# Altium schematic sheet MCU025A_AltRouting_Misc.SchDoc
size 431 x 279 mm; Date: Not shown in title block; ApprovedBy: Not shown in title block; CheckedBy: Not shown in title block; Author: Not shown in title block; CompanyName: Not shown in title block; Engineer: Not shown in title block; Organization: Not shown in title block; Address1: Not shown in title block; Address2: Not shown in title block; Address3: Not shown in title block; Address4: Not shown in title block; DocumentNumber: 3; Revision: Use project parameter SCH_Rev; SheetNumber: 3; SheetTotal: 8; PageSetup: Record=PageOptions¦CenterHorizontal=True¦CenterVertical=True¦PrintScale=1.00¦XCorrection=1.00¦YCorrection=1.00¦PrintKind=0¦BorderSize=5000000¦LeftOffset=0¦BottomOffset=0¦Orientation=2¦PaperLength=1000¦PaperWidth=1000¦Scale=100¦PaperSource=15¦PrintQuality=600¦MediaType=1¦DitherType=10¦PaperKind=Letter¦PrintScaleMode=1
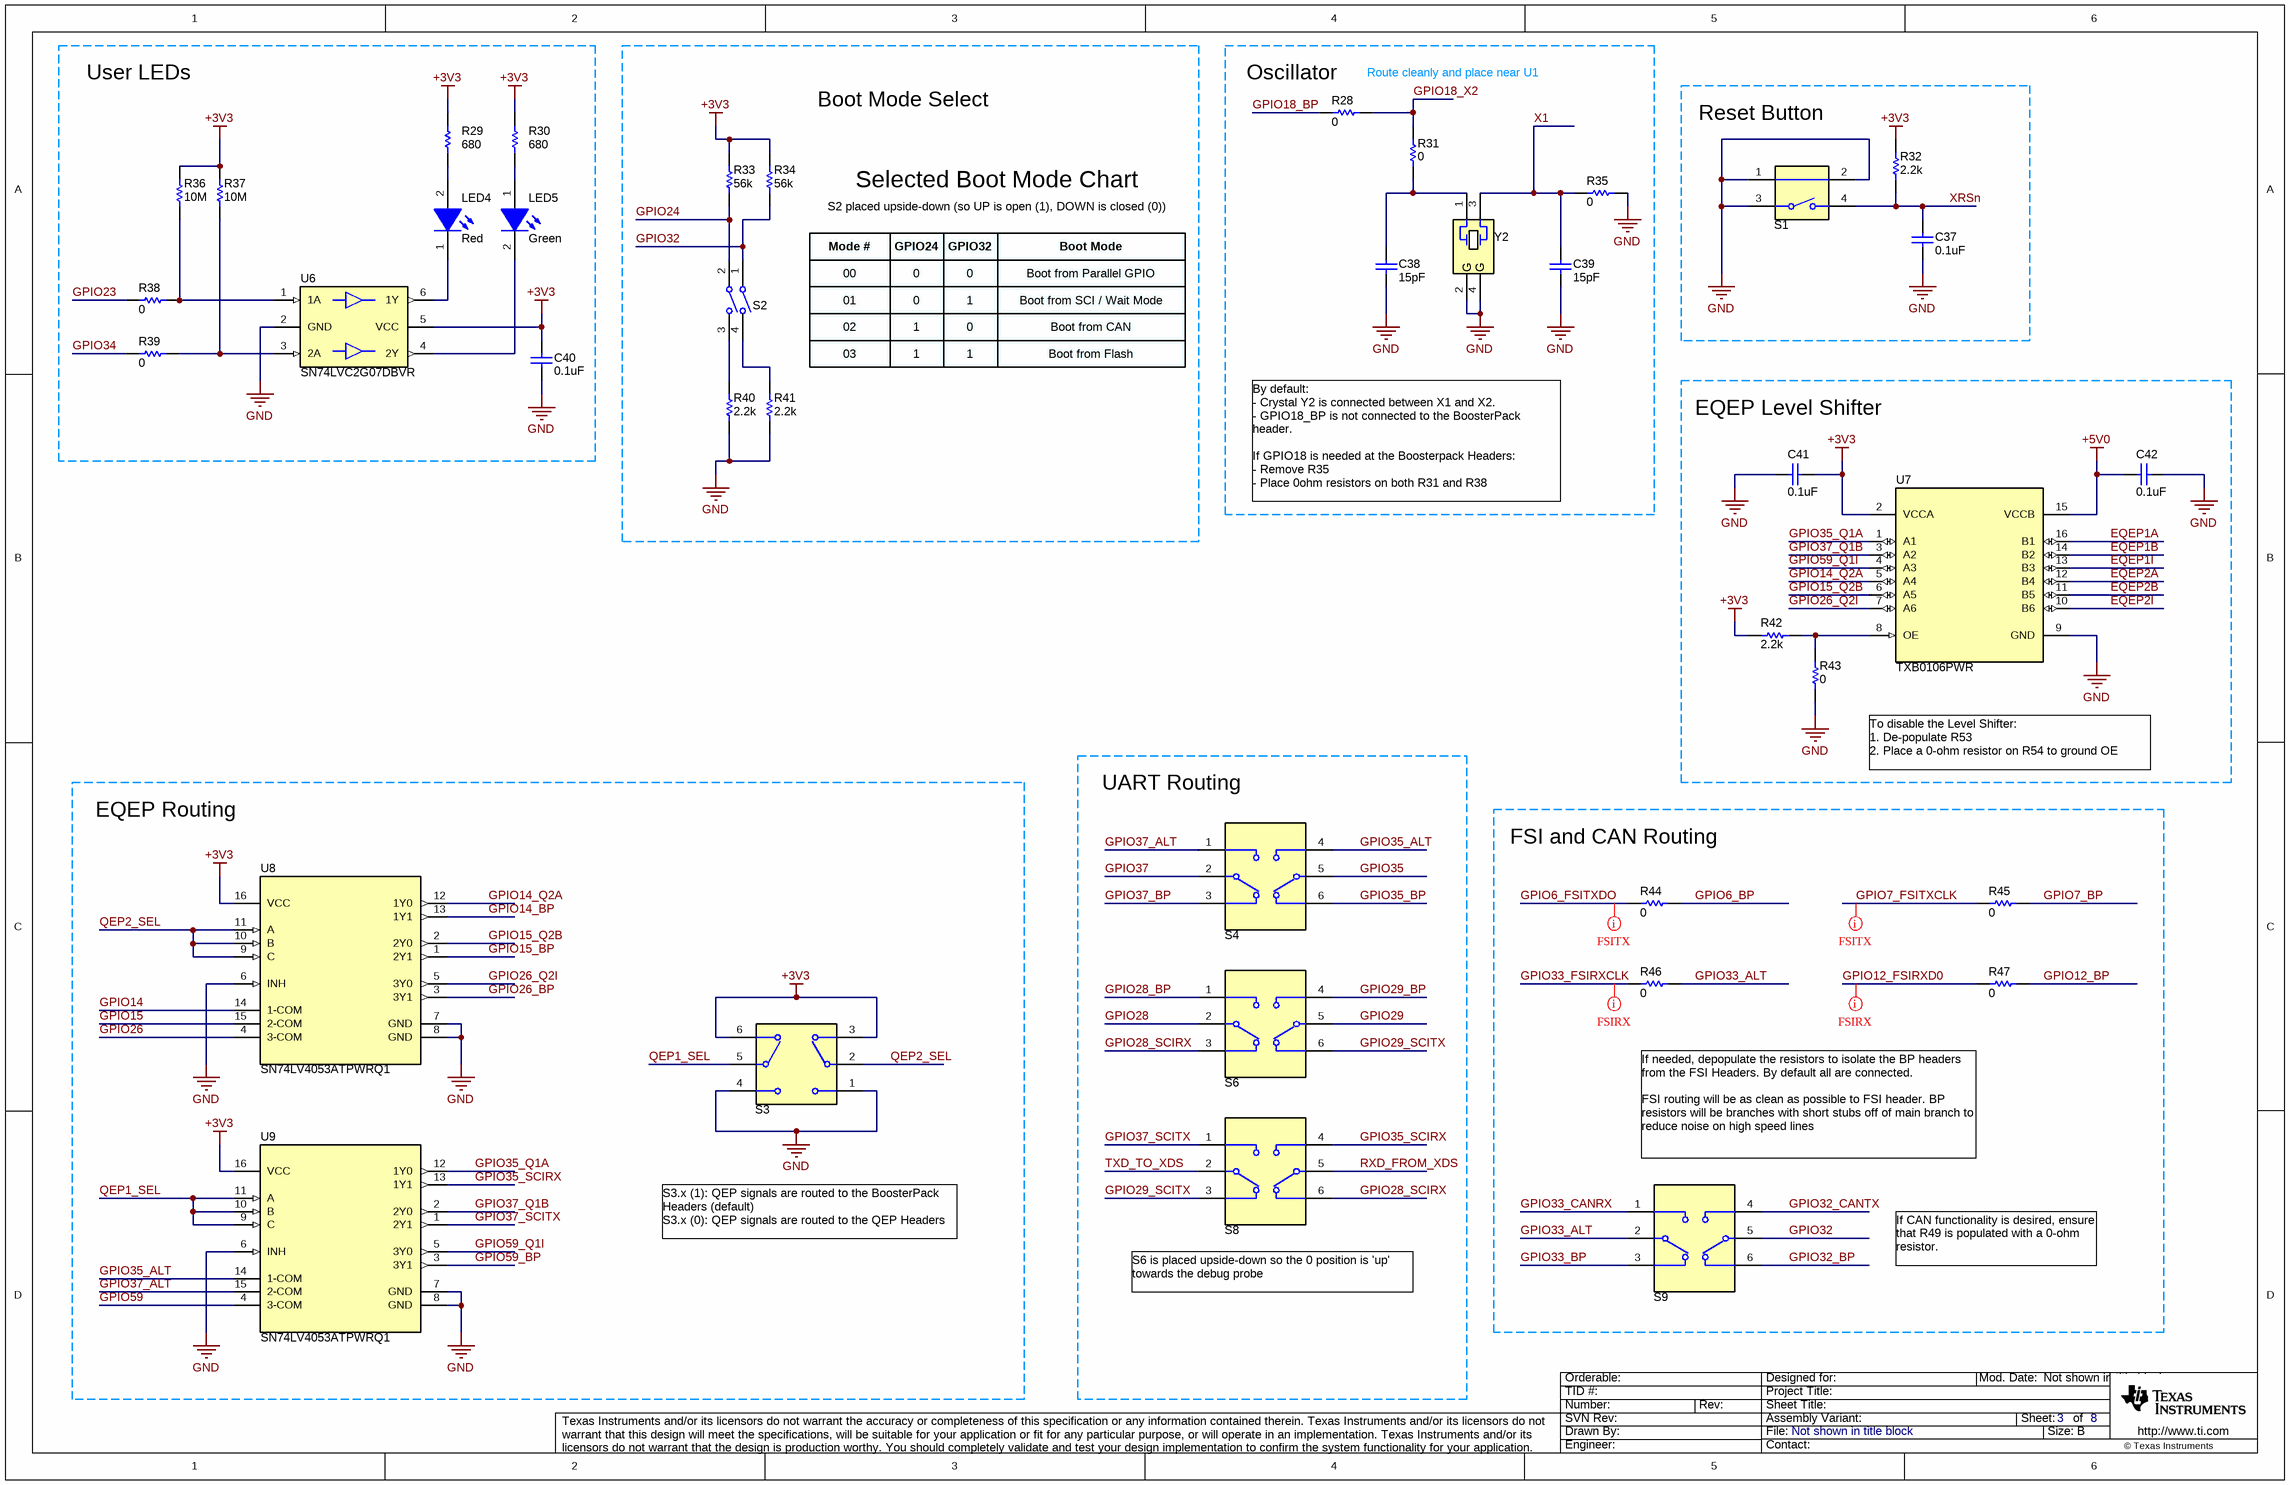
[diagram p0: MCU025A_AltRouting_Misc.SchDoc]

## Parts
C37  ValueDisplayed: 0.1uF  [0402]  (hidden comment: GRM155R71A104KA01D)
C38  ValueDisplayed: 15pF  [0402]  (hidden comment: GRM1555C1H150JA01D)
C39  ValueDisplayed: 15pF  [0402]  (hidden comment: GRM1555C1H150JA01D)
C40  ValueDisplayed: 0.1uF  [0402]  (hidden comment: GRM155R71A104KA01D)
C41  ValueDisplayed: 0.1uF  [0402]  (hidden comment: GRM155R71A104KA01D)
C42  ValueDisplayed: 0.1uF  [0402]  (hidden comment: GRM155R71A104KA01D)
LED4  value Red  [WL-SMCW_RED_0805]  (hidden comment: 150080SS75000)
LED5  value Green  [LED_LTST-C171]  (hidden comment: LTST-C171GKT)
R28  ValueDisplayed: 0  [0603]  (hidden comment: CRCW06030000Z0EA)
R29  ValueDisplayed: 680  [0402]  (hidden comment: CRCW0402680RJNED)
R30  ValueDisplayed: 680  [0402]  (hidden comment: CRCW0402680RJNED)
R31  ValueDisplayed: 0  [0603]  (hidden comment: CRCW06030000Z0EA)
R32  ValueDisplayed: 2.2k  [0402]  (hidden comment: CRCW04022K20JNED)
R33  ValueDisplayed: 56k  [0402]  (hidden comment: CRCW040256K0JNED)
R34  ValueDisplayed: 56k  [0402]  (hidden comment: CRCW040256K0JNED)
R35  ValueDisplayed: 0  [0603]  (hidden comment: CRCW06030000Z0EA)
R36  ValueDisplayed: 10M  [0402]  (hidden comment: CRCW040210M0JNED)
R37  ValueDisplayed: 10M  [0402]  (hidden comment: CRCW040210M0JNED)
R38  ValueDisplayed: 0  [0603]  (hidden comment: CRCW06030000Z0EA)
R39  ValueDisplayed: 0  [0603]  (hidden comment: CRCW06030000Z0EA)
R40  ValueDisplayed: 2.2k  [0402]  (hidden comment: CRCW04022K20JNED)
R41  ValueDisplayed: 2.2k  [0402]  (hidden comment: CRCW04022K20JNED)
R42  ValueDisplayed: 2.2k  [0603]  (hidden comment: CRCW06032K20JNEA)
R43  ValueDisplayed: 0  [0603]  (hidden comment: CRCW06030000Z0EA)
R44  ValueDisplayed: 0  [0603]  (hidden comment: CRCW06030000Z0EA)
R45  ValueDisplayed: 0  [0603]  (hidden comment: CRCW06030000Z0EA)
R46  ValueDisplayed: 0  [0603]  (hidden comment: CRCW06030000Z0EA)
R47  ValueDisplayed: 0  [0603]  (hidden comment: CRCW06030000Z0EA)
S1  1188E-1K2-V-TR  [SW_1188E]  (value not drawn)
S2  218-2LPST  [SW_218-2LP]  (value not drawn)
S3  CAS-D20TA  [SW_CAS-D20TA]  (value not drawn)
S4  CAS-220TA  [SW_CAS-220TA]  (value not drawn)
S6  CAS-220TA  [SW_CAS-220TA]  (value not drawn)
S8  CAS-220TA  [SW_CAS-220TA]  (value not drawn)
S9  CAS-220TA  [SW_CAS-220TA]  (value not drawn)
U6  SN74LVC2G07DBVR  [DBV0006A_N]
U7  TXB0106PWR  [PW0016A_N]
U8  SN74LV4053ATPWRQ1  [PW0016A_L]
U9  SN74LV4053ATPWRQ1  [PW0016A_L]
Y2  ECS-200-18-30B-AGN-TR  [ECS_ECX-53B]  (value not drawn)

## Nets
+3V3: C40.2 C41.1 R29.2 R30.2 R32.2 R33.2 R34.2 R36.2 R37.2 R42.1 S3.3 S3.6 U6.5(VCC) U7.2(VCCA) U8.16(VCC) U9.16(VCC)
+5V0: C42.2 U7.15(VCCB)
GND: C37.1 C38.2 C39.2 C40.1 C41.2 C42.1 R35.2 R40.1 R41.1 R43.1 S1.1 S1.2 S1.3 S3.1 S3.4 U6.2(GND) U7.9(GND) U8.6(INH) U8.7(GND) U8.8(GND) U9.6(INH) U9.7(GND) U9.8(GND) Y2.2(GND) Y2.4(GND)
EQEP1A: U7.16(B1)
EQEP1B: U7.14(B2)
EQEP1I: U7.13(B3)
EQEP2A: U7.12(B4)
EQEP2B: U7.11(B5)
EQEP2I: U7.10(B6)
GPIO6_BP: R44.2
GPIO6_FSITXDO: R44.1
GPIO7_BP: R45.2
GPIO7_FSITXCLK: R45.1
GPIO12_BP: R47.2
GPIO12_FSIRXD0: R47.1
GPIO14: U8.14(1-COM)
GPIO14_BP: U8.13(1Y1)
GPIO14_Q2A: U7.5(A4) U8.12(1Y0)
GPIO15: U8.15(2-COM)
GPIO15_BP: U8.1(2Y1)
GPIO15_Q2B: U7.6(A5) U8.2(2Y0)
GPIO18_BP: R28.1
GPIO18_X2: R28.2 R31.2
GPIO23: R38.1
GPIO24: R33.1 S2.2
GPIO26: U8.4(3-COM)
GPIO26_BP: U8.3(3Y1)
GPIO26_Q2I: U7.7(A6) U8.5(3Y0)
GPIO28: S6.2
GPIO28_BP: S6.1
GPIO28_SCIRX: S6.3 S8.6
GPIO29: S6.5
GPIO29_BP: S6.4
GPIO29_SCITX: S6.6 S8.3
GPIO32: R34.1 S2.1 S9.5
GPIO32_BP: S9.6
GPIO32_CANTX: S9.4
GPIO33_ALT: R46.2 S9.2
GPIO33_BP: S9.3
GPIO33_CANRX: S9.1
GPIO33_FSIRXCLK: R46.1
GPIO34: R39.1
GPIO35: S4.5
GPIO35_ALT: S4.4 U9.14(1-COM)
GPIO35_BP: S4.6
GPIO35_Q1A: U7.1(A1) U9.12(1Y0)
GPIO35_SCIRX: S8.4 U9.13(1Y1)
GPIO37: S4.2
GPIO37_ALT: S4.1 U9.15(2-COM)
GPIO37_BP: S4.3
GPIO37_Q1B: U7.3(A2) U9.2(2Y0)
GPIO37_SCITX: S8.1 U9.1(2Y1)
GPIO59: U9.4(3-COM)
GPIO59_BP: U9.3(3Y1)
GPIO59_Q1I: U7.4(A3) U9.5(3Y0)
QEP1_SEL: S3.5(C) U9.9(C) U9.10(B) U9.11(A)
QEP2_SEL: S3.2(C) U8.9(C) U8.10(B) U8.11(A)
RXD_FROM_XDS: S8.5
TXD_TO_XDS: S8.2
X1: C39.1 R35.1 Y2.3
XRSn: C37.2 R32.1 S1.4
NetC38_1: C38.1 R31.1 Y2.1
NetLED4_1: LED4.1(K) U6.6(1Y)
NetLED4_2: LED4.2(A) R29.1
NetLED5_1: LED5.1(A) R30.1
NetLED5_2: LED5.2(K) U6.4(2Y)
NetR36_1: R36.1 R38.2 U6.1(1A)
NetR37_1: R37.1 R39.2 U6.3(2A)
NetR40_2: R40.2 S2.3
NetR41_2: R41.2 S2.4
NetR42_2: R42.2 R43.2 U7.8(OE)

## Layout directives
net class FSIRX: GPIO12_FSIRXD0, GPIO33_FSIRXCLK
net class FSITX: GPIO6_FSITXDO, GPIO7_FSITXCLK

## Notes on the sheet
- User LEDs
- Boot Mode Select
- (near R28) Oscillator
- (near R28) Route cleanly and place near U1
- Reset Button
- Selected Boot Mode Chart
- (near R34) S2 placed upside-down (so UP is open (1), DOWN is closed (0))
- Mode #
- 00
- 01
- GPIO24
- 0
- GPIO32
- 1
- Boot Mode
- Boot from Parallel GPIO
- Boot from SCI / Wait Mode
- 02
- 03
- Boot from CAN
- Boot from Flash
- EQEP Level Shifter
- By default:
  - Crystal Y2 is connected between X1 and X2.
  - GPIO18_BP is not connected to the BoosterPack header.
  If GPIO18 is needed at the Boosterpack Headers:
  - Remove R35
  - Place 0ohm resistors on both R31 and R38
- To disable the Level Shifter:
  1. De-populate R53
  2. Place a 0-ohm resistor on R54 to ground OE
- EQEP Routing
- UART Routing
- FSI and CAN Routing
- If needed, depopulate the resistors to isolate the BP headers from the FSI Headers. By default all are connected.
  FSI routing will be as clean as possible to FSI header. BP resistors will be branches with short stubs off of main branch to reduce noise on high speed lines
- S3.x (1): QEP signals are routed to the BoosterPack Headers (default)
  S3.x (0): QEP signals are routed to the QEP Headers
- S6 is placed upside-down so the 0 position is 'up' towards the debug probe
- If CAN functionality is desired, ensure that R49 is populated with a 0-ohm resistor.

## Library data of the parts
C37 C40-C42 = CMP-0006629-2: CAP, CERM, 0.1 uF, 10 V, +/- 10%, X7R, 0402; Manufacturer: MuRata; Polarized: N; Value: 0.1uF; U/M: EA; Cap_F: 100nF; Value1: Unknown; VDC_V: 10V; TaMin_C: -55°C; TaMax_C: 125°C; SizeArea_mm2: 0.5; SizeAreaWB_mm2: 3; SizeX_mm: 1; SizeZ_mm: 0.6; AEC Category: Q200
C38 C39 = CMP-0006420-2: CAP, CERM, 15 pF, 50 V, +/- 5%, C0G/NP0, 0402; Manufacturer: MuRata; Polarized: N; Value: 15pF; U/M: EA; Value1: Unknown; VDC_V: 50V; TaMin_C: -55°C; TaMax_C: 125°C; SizeArea_mm2: 0.5; SizeAreaWB_mm2: 3; SizeX_mm: 1; SizeZ_mm: 0.6; AEC Category: Q200
LED4 = CMP-0002951-2: LED, Red, SMD; Manufacturer: Wurth Elektronik; Type: AlInGaP; Vf_V: 1.9V; Io_A: 30mA; Vr_V: 5V; Ir_A: 25µA; Tjmax_C: 85°C; Power_TotalModule: 72mW; Value1: 0.072W; Angle: 140; U/M: EA
LED5 = CMP-0002830-2: LED, Green, SMD; Manufacturer: Lite-On; Type: AlInGaP; Vf_V: 2.1V; Io_A: 20A; Value1: W; SizeAreaWB_mm2: 6.75; SizeArea_mm2: 2.5; SizeX_mm: 2; SizeY_mm: 1.25; SizeZ_mm: 1.2; U/M: EA
R28 R31 R35 R38 R39 R43-R47 = CMP-0025697-4: RES, 0, 5%, 0.1 W, AEC-Q200 Grade 0, 0603; Manufacturer: Vishay-Dale; Value: 0; Value_Code: 0000; Power_W: 100mW; Value2: 0.1W; VDC_V: 75V; TempCo: 200 ppm/C; SizeArea_mm2: 1.28; SizeX_mm: 1.6; SizeY_mm: 0.8; SizeZ_mm: 1; EIA_Code: E24; AEC Category: Q200; AEC Qualified: Y
R29 R30 = CMP-0026962-3: RES, 680, 5%, 0.063 W, AEC-Q200 Grade 0, 0402; Manufacturer: Vishay-Dale; Power_W: 63mW; TempCo: 200 ppm/C; Value_Code: 680R; Value: 680; EIA_Code: E24; SizeX_mm: 1; SizeY_mm: 0.5; SizeZ_mm: 0.6; Value2: 0.063W; CompType: Resistor; AEC Qualified: Y; VDC_V: 50V; AEC Category: Q200; AEC Grade: 0
R32 R40 R41 = CMP-0026890-5: RES, 2.2 k, 5%, 0.063 W, AEC-Q200 Grade 0, 0402; Manufacturer: Vishay-Dale; Value: 2.2k; Value_Code: 2k20; Power_W: 63mW; Value2: 0.063W; VDC_V: 50V; TempCo: 200 ppm/C; SizeArea_mm2: 0.5; SizeX_mm: 1; SizeZ_mm: 0.6; EIA_Code: E24; AEC Category: Q200; AEC Qualified: Y; AEC Grade: 0
R33 R34 = CMP-0026949-3: RES, 56 k, 5%, 0.063 W, AEC-Q200 Grade 0, 0402; Manufacturer: Vishay-Dale; Value: 56k; Value_Code: 56k0; Power_W: 63mW; Value2: 0.063W; VDC_V: 50V; TempCo: 200 ppm/C; SizeArea_mm2: 0.5; SizeX_mm: 1; SizeZ_mm: 0.6; EIA_Code: E24; AEC Category: Q200; AEC Qualified: Y; AEC Grade: 0
R36 R37 = CMP-0026826-2: RES, 10 M, 5%, 0.063 W, AEC-Q200 Grade 0, 0402; Manufacturer: Vishay-Dale; Value: 10Meg; Value_Code: 10M0; Power_W: 63mW; Value2: 0.063W; VDC_V: 50V; TempCo: 200 ppm/C; SizeArea_mm2: 0.5; SizeX_mm: 1; SizeZ_mm: 0.6; EIA_Code: E24; AEC Category: Q200; AEC Qualified: Y; AEC Grade: 0
R42 = CMP-0025769-4: RES, 2.2 k, 5%, 0.1 W, AEC-Q200 Grade 0, 0603; Manufacturer: Vishay-Dale; Value: 2.2k; Value_Code: 2k20; Power_W: 100mW; Value2: 0.1W; VDC_V: 75V; TempCo: 200 ppm/C; SizeArea_mm2: 1.28; SizeX_mm: 1.6; SizeY_mm: 0.8; SizeZ_mm: 1; EIA_Code: E24; AEC Category: Q200; AEC Qualified: Y; AEC Grade: 0
S1 = CMP-0002328-1: Switch, SPST, 0.05 A, 12 VDC, SMD; Manufacturer: Diptronics; SizeAreaWB_mm2: 53.9; SizeArea_mm2: 27.3; SizeX_mm: 7.8; SizeY_mm: 3.5; VDC_V: 12V; PositionCount: 1; CurrentRating_mA: 50A
S2 = CMP-0002230-1: Switch, SPST, 2 Pos, 25mA, 24VDC, SMD; Manufacturer: CTS Electrocomponents; VDC_V: 24V; SwitchFunction: Off-On; PositionCount: 2; CurrentRating_mA: 25A
S3 = CMP-0002233-1: Switch, Dual SPDT,  2 Pos, 0.1A, 6VDC, SMD; Manufacturer: Copal Electronics; VDC_V: 6V; SwitchFunction: On-On; PositionCount: 2; CurrentRating_mA: 100A
S4 S6 S8 S9 = CMP-0002123-2: SLIDE SWITCH DPDT  .1A, SMT; Manufacturer: Copal Electronics; VDC_V: 6V; SwitchFunction: On-On; PositionCount: 2; CurrentRating_mA: 100A
U6 = CMP-0051789-2: Dual Buffer/Driver with Open-Drain Output, DBV0006A, LARGE T&R; Manufacturer: Texas Instruments; VCC(Min)(V): 1.65; VCC(Max)(V): 5.5; Output Type: CMOS; ICC @ Nom Voltage(Max)(mA): 0.01; Input Type: CMOS/TTL; Bits(#): 2; F @ Nom Voltage(Max)(Mhz): 150; Rating: Catalog; Technology Family: LVC; Voltage(Nom)(V): 1.8,2.5,3.3,5; Schmitt Trigger: No; Output Drive (IOL/IOH)(Max)(mA): 32/-32; tpd @ Nom Voltage(Max)(ns): 8.6,4.4,3.7,2.9; Logic: True; Sub-Family: Inverting Buffer/Driver; AEC Category: Q200; AEC Qualified: N; CompType: IC; Green_Lifecycle: Active; Green_REACh: Passed; SizeArea_mm2: 8.12; SizeAreaWB_mm2: 14.82; SizeX_mm: 2.8; SizeY_mm: 2.9; SizeZ_mm: 1.45
U7 = CMP-0067443-1: 6-Bit Bidirectional Voltage-Level Translator with Auto Direction Sensing and +/-15-kV ESD Protect, PW0016A (TSSOP-16); Manufacturer: Texas Instruments; SizeArea_mm2: 32.0; SizeAreaWB_mm2: 58.8; SizeX_mm: 6.4; SizeY_mm: 5.0; SizeZ_mm: 1.2; CompType: IC; U/M: EA; Green_Lifecycle: Active; Green_REACh: Passed
U8 U9 = CMP-0076549-1: TRIPLE 2-CHANNEL ANALOG MULTIPLEXER/DEMULTIPLEXER, PW0016A (TSSOP-16); Manufacturer: Texas Instruments; SizeAreaWB_mm2: 58.8; SizeArea_mm2: 32.0; SizeZ_mm: 1.2; SizeY_mm: 5.0; U/M: EA; CompType: IC; SizeX_mm: 6.4
Y2 = CMP-0080365-1: Crystal, 20 MHz, 25 ppm, 18, SMD; Manufacturer: ECS Inc.; Frequency Stability: 30 ppm; AEC Qualified: N; Frequency Tolerance: 25 ppm; AEC Category: Q200; TaMax_C: 85°C; Frequency_Fixed: 20MHz; TaMin_C: -40°C; Load Capacitance: 18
